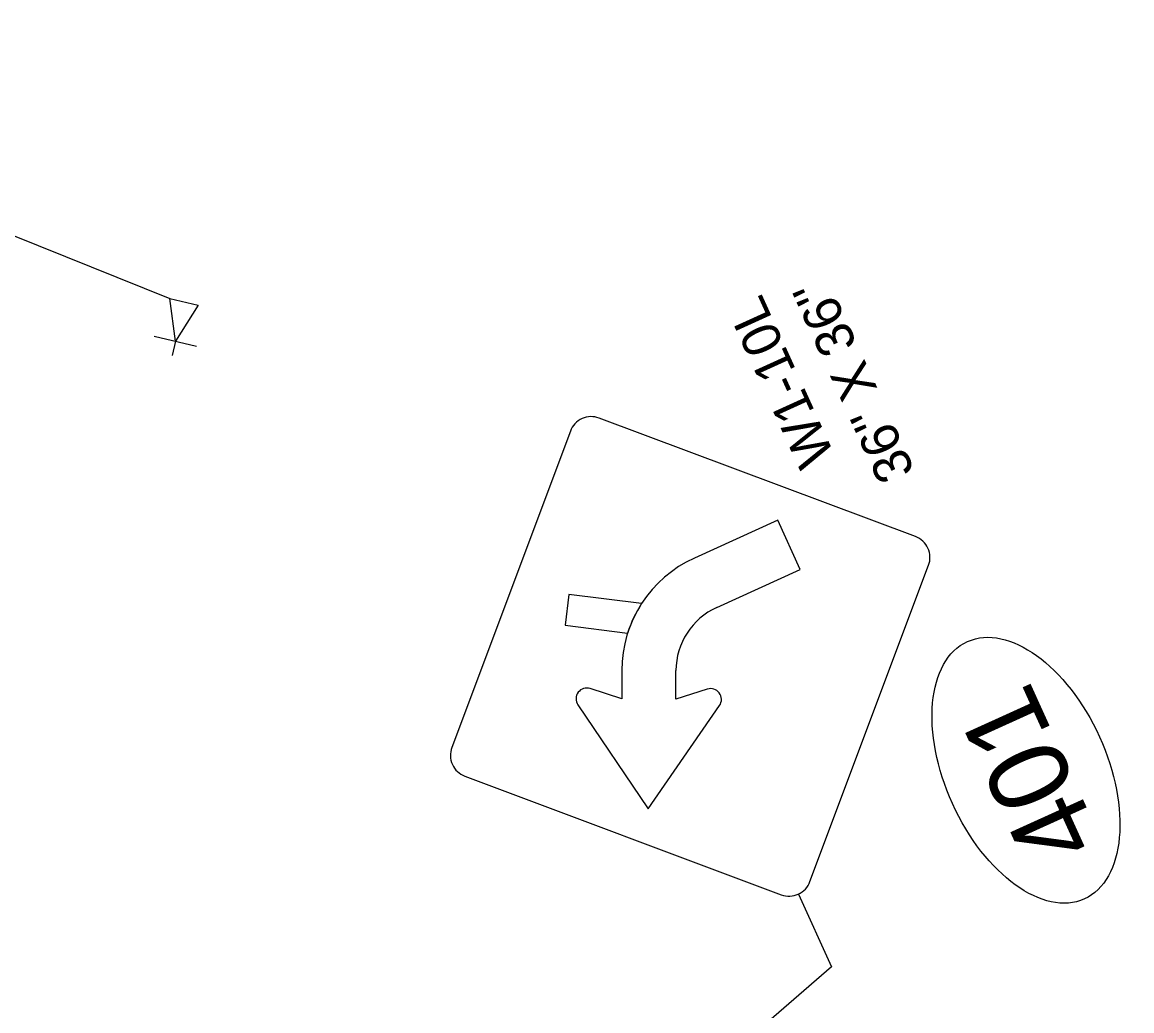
# Model space of a CAD drawing. Extents: x 2093420 to 2100301, y 676254 to 688367.
# Drawn here: x 2096654 to 2096828.1, y 683750.8 to 683905.9 of the extents above; entities that cross this region are included whole.
import ezdxf

# ---------------------------------------------------------------- set-up
doc = ezdxf.new("R2010")
doc.units = 0
doc.layers.add('Default', color=7, linetype='Continuous')
doc.layers.add('Prop DSN Text', color=7, linetype='Continuous')

msp = doc.modelspace()

# ---------------------------------------------------------------- linework, layer by layer
at = {"layer": 'Default'}
for p, q in [((2096678.09, 683855.85), (2096677.19, 683862.53)), ((2096677.19, 683862.53), (2096681.64, 683861.49)), ((2096681.64, 683861.49), (2096678.09, 683855.85)), ((2096674.75, 683856.64), (2096681.38, 683855.08)), ((2096678.09, 683855.85), (2096677.56, 683853.6))]:
    msp.add_line(p, q, dxfattribs=at)
for points in [[(2096607.03, 683905.9), (2096615.44, 683887.4), (2096677.19, 683862.53)], [(2096775.78, 683769.09), (2096780.98, 683757.66), (2096678.98, 683669.21)]]:
    msp.add_lwpolyline(points, dxfattribs=at)
msp.add_ellipse((2096811.49, 683788.53), major_axis=(9.17, -20.19), ratio=0.571429, dxfattribs=at)
at = {"layer": 'Prop DSN Text'}
for p, q in [((2096794.16, 683825.19), (2096744.53, 683843.79)), ((2096739.79, 683816.1), (2096739.19, 683811.27)), ((2096751.2, 683814.68), (2096739.79, 683816.1)), ((2096739.19, 683811.27), (2096749, 683810.05)), ((2096756.56, 683804.04), (2096756.55, 683804.02)), ((2096741.2, 683798.78), (2096741.21, 683798.78)), ((2096741.21, 683798.78), (2096752.23, 683782.47)), ((2096752.23, 683782.47), (2096763.42, 683798.68))]:
    msp.add_line(p, q, dxfattribs=at)
for points in [[(2096740.02, 683841.74), (2096721.42, 683792.11)], [(2096762.99, 683814.07), (2096776.09, 683820.02), (2096772.57, 683827.76), (2096759.47, 683821.81)], [(2096777.61, 683771.05), (2096796.21, 683820.68)], [(2096748.09, 683804.2), (2096748.07, 683799.73), (2096743.14, 683801.35)], [(2096761.5, 683801.26), (2096756.57, 683799.69), (2096756.59, 683804.16)], [(2096723.47, 683787.6), (2096773.1, 683769)]]:
    msp.add_lwpolyline(points, dxfattribs=at)
for centre, radius, start, end in [((2096743.3, 683840.51), 3.5, 69.458, 159.458), ((2096792.93, 683821.91), 3.5, 24.458, 69.458), ((2096792.93, 683821.91), 3.5, 339.458, 24.458), ((2096767.52, 683804.11), 19.45, 114.4274, 179.7345), ((2096767.52, 683804.11), 19.45, 147.081, 162.2078), ((2096767.52, 683804.11), 10.94, 114.4274, 179.7345), ((2096742.61, 683799.73), 1.7, 71.9367, 214.0587), ((2096762.02, 683799.64), 1.7, 325.4103, 107.5388), ((2096724.7, 683790.88), 3.5, 159.445, 204.4515), ((2096724.7, 683790.88), 3.5, 204.4515, 249.458), ((2096774.33, 683772.28), 3.5, 249.458, 339.458)]:
    msp.add_arc(centre, radius, start, end, dxfattribs=at)

# ---------------------------------------------------------------- texts
at = {"layer": 'Default'}
msp.add_text('401', height=12.516, rotation=114.4239, dxfattribs=at).set_placement((2096823.41, 683777.42))
at = {"layer": 'Prop DSN Text'}
for s, p in [('W1-10L', (2096781.57, 683837.85)), ("36'' X 36''", (2096794.14, 683835.42))]:
    msp.add_text(s, height=6, rotation=114.458, dxfattribs=at).set_placement(p)

doc.saveas('drawing.dxf')
